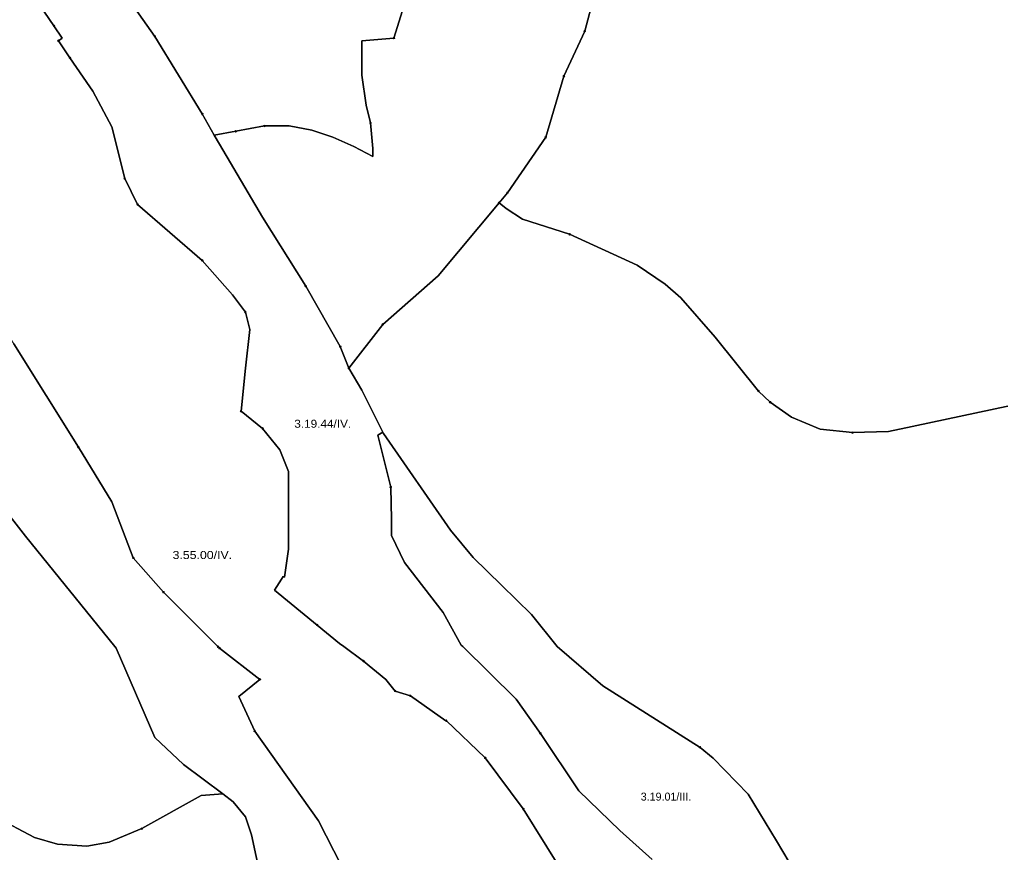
# Model space of a CAD drawing. Extents: x -650455 to -642254, y -1075222 to -1066610.
# Drawn here: x -646878 to -645652, y -1072257 to -1071216 of the extents above; entities that cross this region are included whole.
import ezdxf
from ezdxf.enums import TextEntityAlignment as Align

# ---------------------------------------------------------------- set-up
doc = ezdxf.new("R2010")
doc.units = 0
doc.header["$LTSCALE"] = 4
doc.header["$PDMODE"] = 32
doc.header["$PDSIZE"] = 2
for name, color, linetype, lineweight in [('1', 7, 'Continuous', 25), ('11', 7, 'Continuous', 13), ('12', 7, 'Continuous', 13), ('13', 7, 'Continuous', 13), ('14', 7, 'Continuous', 13)]:
    doc.layers.add(name, color=color, linetype=linetype, lineweight=lineweight)
doc.layers.add('2', color=7, linetype='Continuous')

msp = doc.modelspace()

# ---------------------------------------------------------------- linework, layer by layer
at = {"layer": '1'}
for points in [[(-646154.372, -1071165.527), (-646171.706, -1071230.527), (-646197.706, -1071286.861), (-646220.456, -1071363.237), (-646268.124, -1071432.571), (-646278.639, -1071445.19), (-646354.791, -1071536.572), (-646424.125, -1071597.24), (-646466.433, -1071651.884), (-646477.206, -1071624.953), (-646520.295, -1071549.547), (-646574.157, -1071463.368), (-646628.018, -1071371.803), (-646634.506, -1071360.45), (-646607.539, -1071355.754), (-646571.854, -1071349.129), (-646541.062, -1071349.053), (-646512.831, -1071354.248), (-646486.255, -1071363.056), (-646460.282, -1071374.876)], [(-646190.5, -1071484.501), (-646249.5, -1071465.5), (-646270, -1071452.5), (-646278.639, -1071445.19), (-646268.124, -1071432.571), (-646220.456, -1071363.237), (-646197.706, -1071286.861), (-646171.706, -1071230.527), (-646154.372, -1071165.527)], [(-646393.156, -1071184.317), (-646410.042, -1071239.194), (-646450.275, -1071242.536), (-646450.275, -1071285.625), (-646444.889, -1071323.328), (-646439.373, -1071345.392), (-646436.341, -1071377.436), (-646436.341, -1071387.223), (-646460.282, -1071374.876), (-646486.255, -1071363.056), (-646512.831, -1071354.248), (-646541.062, -1071349.053), (-646571.854, -1071349.129), (-646607.539, -1071355.754), (-646634.506, -1071360.45), (-646649.563, -1071334.1), (-646708.811, -1071237.149), (-646743.712, -1071187.194)], [(-646743.712, -1071187.194), (-646708.811, -1071237.149), (-646649.563, -1071334.1), (-646634.506, -1071360.45), (-646628.018, -1071371.803), (-646574.157, -1071463.368), (-646520.295, -1071549.547), (-646477.206, -1071624.953), (-646466.433, -1071651.884), (-646450.126, -1071679.574), (-646423.791, -1071731.896), (-646430, -1071735.501), (-646414, -1071800.501), (-646413, -1071841.001), (-646413, -1071861.001), (-646397, -1071895), (-646348.5, -1071957.501)], [(-646460.282, -1071374.876), (-646436.341, -1071387.223), (-646436.341, -1071377.436), (-646439.373, -1071345.392), (-646444.889, -1071323.328), (-646450.275, -1071285.625), (-646450.275, -1071242.536), (-646410.042, -1071239.194), (-646393.156, -1071184.317)], [(-646786.429, -1071305.826), (-646790.183, -1071300.284), (-646814.876, -1071263.836), (-646829.299, -1071242.546), (-646824.502, -1071239.296), (-646834.862, -1071224.003), (-646859.12, -1071188.198)], [(-646859.12, -1071188.198), (-646834.862, -1071224.003), (-646824.502, -1071239.296), (-646829.299, -1071242.546), (-646814.876, -1071263.836), (-646790.183, -1071300.284), (-646786.429, -1071305.826), (-646762.673, -1071350.259), (-646746.514, -1071414.893), (-646730.355, -1071447.21), (-646649.563, -1071517.23), (-646611.86, -1071560.319), (-646595.701, -1071581.864), (-646590.315, -1071603.408), (-646595.701, -1071651.884), (-646601.087, -1071705.746), (-646574.157, -1071727.29), (-646552.612, -1071754.221), (-646541.84, -1071781.152), (-646541.84, -1071829.627), (-646541.84, -1071878.103), (-646546.839, -1071913.101), (-646548.5, -1071912.501), (-646550.686, -1071915.879)], [(-646175.5, -1072320), (-646248.5, -1072203), (-646296, -1072139.001), (-646345, -1072092.5), (-646345.4, -1072092.965), (-646389.5, -1072061.5), (-646408.5, -1072055.501), (-646420, -1072041), (-646448, -1072018.001), (-646472.545, -1072000), (-646478, -1071996), (-646506, -1071973.001), (-646559.5, -1071929.501), (-646550.686, -1071915.879), (-646548.5, -1071912.501), (-646546.839, -1071913.101), (-646541.84, -1071878.103), (-646541.84, -1071829.627), (-646541.84, -1071781.152), (-646552.612, -1071754.221), (-646574.157, -1071727.29), (-646601.087, -1071705.746), (-646595.701, -1071651.884), (-646590.315, -1071603.408), (-646595.701, -1071581.864), (-646611.86, -1071560.319), (-646649.563, -1071517.23), (-646730.355, -1071447.21), (-646746.514, -1071414.893), (-646762.673, -1071350.259), (-646786.429, -1071305.826)], [(-645908.5, -1072283), (-645932, -1072243), (-645967.5, -1072184.501), (-646011, -1072139.501), (-646027.5, -1072126), (-646149, -1072049), (-646206, -1072000), (-646238, -1071960), (-646275.5, -1071923), (-646311, -1071888.501), (-646339.5, -1071854.5), (-646423.033, -1071733.402), (-646423.791, -1071731.896), (-646450.126, -1071679.574), (-646466.433, -1071651.884), (-646424.125, -1071597.24), (-646354.791, -1071536.572), (-646278.639, -1071445.19), (-646270, -1071452.5), (-646249.5, -1071465.5), (-646190.5, -1071484.501), (-646106, -1071523), (-646071, -1071547), (-646051.5, -1071564.001), (-646008.5, -1071613.001), (-645954.5, -1071680.5), (-645940, -1071694.501), (-645913.5, -1071713), (-645877.5, -1071728), (-645837, -1071732.5), (-645792, -1071731.001), (-645762.5, -1071725), (-645619.5, -1071694.501)], [(-645619.5, -1071694.501), (-645762.5, -1071725), (-645792, -1071731.001), (-645837, -1071732.5), (-645877.5, -1071728), (-645913.5, -1071713), (-645940, -1071694.501), (-645954.5, -1071680.5), (-646008.5, -1071613.001), (-646051.5, -1071564.001), (-646071, -1071547), (-646106, -1071523), (-646190.5, -1071484.501)], [(-646447, -1072330.501), (-646504.5, -1072218), (-646584, -1072105.5), (-646604, -1072062.501), (-646577.5, -1072041), (-646628.018, -1072001.985), (-646630.002, -1072000), (-646698.038, -1071931.964), (-646735.742, -1071888.875), (-646762.673, -1071818.855), (-646804.415, -1071750.855), (-646885.208, -1071621.587)], [(-646885.208, -1071621.587), (-646804.415, -1071750.855), (-646762.673, -1071818.855), (-646735.742, -1071888.875), (-646698.038, -1071931.964), (-646630.002, -1072000), (-646628.018, -1072001.985), (-646577.5, -1072041), (-646604, -1072062.501), (-646584, -1072105.5), (-646504.5, -1072218), (-646447, -1072330.501)], [(-646087.5, -1072266.001), (-646128, -1072230), (-646179, -1072180.501), (-646227, -1072108.5), (-646257.5, -1072065.5), (-646323.97, -1072000), (-646326, -1071998.001), (-646348.5, -1071957.501), (-646397, -1071895), (-646413, -1071861.001), (-646413, -1071841.001), (-646414, -1071800.501), (-646430, -1071735.501), (-646423.791, -1071731.896), (-646423.033, -1071733.402), (-646339.5, -1071854.5), (-646311, -1071888.501), (-646275.5, -1071923), (-646238, -1071960), (-646206, -1072000), (-646149, -1072049), (-646027.5, -1072126), (-646011, -1072139.501), (-645967.5, -1072184.501), (-645932, -1072243), (-645908.5, -1072283)], [(-646611, -1072194), (-646624, -1072184.001), (-646673, -1072147.501), (-646709, -1072113.5), (-646757.286, -1072001.985), (-646758.889, -1072000), (-646870.396, -1071861.944), (-646929.643, -1071786.538)], [(-646929.643, -1071786.538), (-646870.396, -1071861.944), (-646758.889, -1072000), (-646757.286, -1072001.985), (-646709, -1072113.5), (-646673, -1072147.501), (-646624, -1072184.001), (-646651, -1072186), (-646725, -1072227.5), (-646766, -1072244.501), (-646794, -1072249.501), (-646830.5, -1072247), (-646859, -1072238.5), (-646908.5, -1072213.001)], [(-646550.686, -1071915.879), (-646559.5, -1071929.501), (-646506, -1071973.001), (-646478, -1071996), (-646472.545, -1072000), (-646448, -1072018.001), (-646420, -1072041), (-646408.5, -1072055.501), (-646389.5, -1072061.5), (-646345.4, -1072092.965), (-646345, -1072092.5), (-646296, -1072139.001), (-646248.5, -1072203), (-646175.5, -1072320), (-646120.5, -1072383.001), (-646020, -1072481), (-646013.29, -1072487.101)], [(-646348.5, -1071957.501), (-646326, -1071998.001), (-646323.97, -1072000), (-646257.5, -1072065.5), (-646227, -1072108.5), (-646179, -1072180.501), (-646128, -1072230), (-646087.5, -1072266.001)], [(-646908.5, -1072213.001), (-646859, -1072238.5), (-646830.5, -1072247), (-646794, -1072249.501), (-646766, -1072244.501), (-646725, -1072227.5), (-646651, -1072186), (-646624, -1072184.001), (-646611, -1072194), (-646595.5, -1072213.001), (-646588, -1072235.5), (-646576.5, -1072289.501), (-646559.5, -1072345.501), (-646540.5, -1072384), (-646514.5, -1072420.001), (-646470, -1072469.5), (-646420, -1072512.501), (-646392, -1072535), (-646381, -1072550.5), (-646346.5, -1072604.501), (-646329.469, -1072644.503), (-646334, -1072702.501), (-646348, -1072738.501), (-646368, -1072765.5)], [(-646576.5, -1072289.501), (-646588, -1072235.5), (-646595.5, -1072213.001), (-646611, -1072194)]]:
    msp.add_lwpolyline(points, dxfattribs=at)
at = {"layer": '11'}
for p, q in [((-646197.706, -1071286.861), (-646220.456, -1071363.237)), ((-646220.456, -1071363.237), (-646268.124, -1071432.571)), ((-646630.002, -1072000), (-646698.038, -1071931.964))]:
    msp.add_line(p, q, dxfattribs=at)
for points in [[(-646197.487, -1070763.107), (-646171.706, -1070831.857), (-646145.706, -1070901.191), (-646141.372, -1070996.525), (-646145.706, -1071100.526), (-646154.372, -1071165.527), (-646171.706, -1071230.527), (-646197.706, -1071286.861)], [(-646268.124, -1071432.571), (-646278.639, -1071445.19), (-646270, -1071452.5), (-646249.5, -1071465.5), (-646190.5, -1071484.501)], [(-646698.038, -1071931.964), (-646735.742, -1071888.875), (-646762.673, -1071818.855), (-646804.415, -1071750.855), (-646885.208, -1071621.587), (-646992.931, -1071454.616)], [(-645954.5, -1071680.5), (-646008.5, -1071613.001), (-646051.5, -1071564.001), (-646071, -1071547), (-646106, -1071523), (-646190.5, -1071484.501), (-646249.5, -1071465.5), (-646270, -1071452.5), (-646278.639, -1071445.19), (-646354.791, -1071536.572), (-646424.125, -1071597.24), (-646466.433, -1071651.884)], [(-646190.5, -1071484.501), (-646106, -1071523), (-646071, -1071547), (-646051.5, -1071564.001), (-646008.5, -1071613.001), (-645954.5, -1071680.5), (-645940, -1071694.501)], [(-646466.433, -1071651.884), (-646450.126, -1071679.574), (-646423.791, -1071731.896), (-646423.033, -1071733.402), (-646339.5, -1071854.5), (-646311, -1071888.501), (-646275.5, -1071923), (-646238, -1071960), (-646206, -1072000), (-646149, -1072049), (-646027.5, -1072126)], [(-645837, -1071732.5), (-645792, -1071731.001), (-645762.5, -1071725), (-645619.5, -1071694.501), (-645493, -1071675.001), (-645451, -1071667.001), (-645411, -1071663), (-645381.5, -1071666.001), (-645306, -1071694.501)], [(-645493, -1071675.001), (-645619.5, -1071694.501), (-645762.5, -1071725), (-645792, -1071731.001), (-645837, -1071732.5), (-645877.5, -1071728), (-645913.5, -1071713), (-645940, -1071694.501), (-645954.5, -1071680.5)], [(-645940, -1071694.501), (-645913.5, -1071713), (-645877.5, -1071728), (-645837, -1071732.5)], [(-646908.5, -1072213.001), (-646859, -1072238.5), (-646830.5, -1072247), (-646794, -1072249.501), (-646766, -1072244.501), (-646725, -1072227.5), (-646651, -1072186), (-646624, -1072184.001), (-646673, -1072147.501), (-646709, -1072113.5), (-646757.286, -1072001.985), (-646758.889, -1072000), (-646870.396, -1071861.944), (-646929.643, -1071786.538)], [(-646929.643, -1071786.538), (-646870.396, -1071861.944), (-646758.889, -1072000), (-646757.286, -1072001.985), (-646709, -1072113.5), (-646673, -1072147.501), (-646624, -1072184.001), (-646611, -1072194), (-646595.5, -1072213.001), (-646588, -1072235.5), (-646576.5, -1072289.501), (-646559.5, -1072345.501), (-646540.5, -1072384)], [(-646584, -1072105.5), (-646604, -1072062.501), (-646577.5, -1072041), (-646628.018, -1072001.985), (-646630.002, -1072000)], [(-646725, -1072227.5), (-646766, -1072244.501), (-646794, -1072249.501), (-646830.5, -1072247), (-646859, -1072238.5), (-646908.5, -1072213.001), (-646971, -1072165.5), (-647106.5, -1072039.5)], [(-646346.5, -1072527.501), (-646337, -1072520.001), (-646337, -1072506), (-646381, -1072447.501), (-646419.5, -1072388.5), (-646447, -1072330.501), (-646504.5, -1072218), (-646584, -1072105.5)], [(-646027.5, -1072126), (-646011, -1072139.501), (-645967.5, -1072184.501), (-645932, -1072243), (-645908.5, -1072283), (-645884.5, -1072309.501), (-645854, -1072327), (-645788.5, -1072351.001), (-645718.5, -1072394.001), (-645697, -1072391.501), (-645594, -1072384.5), (-645567.5, -1072387.001), (-645560, -1072390.001), (-645550.5, -1072338.001), (-645549, -1072189.5), (-645544.5, -1072153.5), (-645532, -1072135.501), (-645510.5, -1072118.5), (-645474.5, -1072111.501), (-645421, -1072113), (-645398, -1072117), (-645373.5, -1072126), (-645338.5, -1072147.001)], [(-646559.5, -1072345.501), (-646576.5, -1072289.501), (-646588, -1072235.5), (-646595.5, -1072213.001), (-646611, -1072194), (-646624, -1072184.001), (-646651, -1072186), (-646725, -1072227.5)]]:
    msp.add_lwpolyline(points, dxfattribs=at)
for p in [(-646197.706, -1071286.861), (-646220.456, -1071363.237), (-646268.124, -1071432.571), (-646190.5, -1071484.501), (-646466.433, -1071651.884), (-645954.5, -1071680.5), (-645940, -1071694.501), (-645837, -1071732.5), (-646698.038, -1071931.964), (-646630.002, -1072000), (-646584, -1072105.5), (-646027.5, -1072126), (-646725, -1072227.5)]:
    msp.add_point(p, dxfattribs=at)
at = {"layer": '12'}
for p, q in [((-646197.706, -1071286.861), (-646171.706, -1071230.527)), ((-646278.639, -1071445.19), (-646268.124, -1071432.571))]:
    msp.add_line(p, q, dxfattribs=at)
for points in [[(-646171.706, -1071230.527), (-646154.372, -1071165.527), (-646145.706, -1071100.526), (-646141.372, -1070996.525), (-646145.706, -1070901.191), (-646171.706, -1070831.857), (-646197.487, -1070763.107), (-646197.659, -1070749.898)], [(-646396.096, -1071025.528), (-646393.156, -1071184.317), (-646410.042, -1071239.194)], [(-646410.042, -1071239.194), (-646450.275, -1071242.536), (-646450.275, -1071285.625), (-646444.889, -1071323.328), (-646439.373, -1071345.392)], [(-646268.124, -1071432.571), (-646220.456, -1071363.237), (-646197.706, -1071286.861)], [(-646439.373, -1071345.392), (-646436.341, -1071377.436), (-646436.341, -1071387.223), (-646460.282, -1071374.876), (-646486.255, -1071363.056), (-646512.831, -1071354.248), (-646541.062, -1071349.053), (-646571.854, -1071349.129), (-646607.539, -1071355.754), (-646634.506, -1071360.45), (-646628.018, -1071371.803), (-646574.157, -1071463.368), (-646520.295, -1071549.547), (-646477.206, -1071624.953)], [(-646424.125, -1071597.24), (-646354.791, -1071536.572), (-646278.639, -1071445.19)], [(-646477.206, -1071624.953), (-646466.433, -1071651.884), (-646424.125, -1071597.24)]]:
    msp.add_lwpolyline(points, dxfattribs=at)
for p in [(-646171.706, -1071230.527), (-646410.042, -1071239.194), (-646197.706, -1071286.861), (-646439.373, -1071345.392), (-646268.124, -1071432.571), (-646278.639, -1071445.19), (-646424.125, -1071597.24), (-646477.206, -1071624.953)]:
    msp.add_point(p, dxfattribs=at)
at = {"layer": '13'}
for p, q in [((-646708.811, -1071237.149), (-646649.563, -1071334.1)), ((-646607.539, -1071355.754), (-646571.854, -1071349.129))]:
    msp.add_line(p, q, dxfattribs=at)
for points in [[(-646677.628, -1070751.147), (-646699.295, -1070738.147), (-646729.628, -1070720.814), (-646751.296, -1070768.481), (-646768.629, -1070811.815), (-646799.029, -1070883.683), (-646815.187, -1070905.227), (-646831.346, -1070932.158), (-646869.049, -1070964.475), (-646804.415, -1071034.495), (-646782.712, -1071061.526), (-646782.712, -1071100.526), (-646769.712, -1071135.193), (-646743.712, -1071187.194), (-646708.811, -1071237.149)], [(-646410.042, -1071239.194), (-646393.156, -1071184.317), (-646396.096, -1071025.528), (-646392.694, -1071012.768)], [(-646571.854, -1071349.129), (-646541.062, -1071349.053), (-646512.831, -1071354.248), (-646486.255, -1071363.056), (-646460.282, -1071374.876), (-646436.341, -1071387.223), (-646436.341, -1071377.436), (-646439.373, -1071345.392), (-646444.889, -1071323.328), (-646450.275, -1071285.625), (-646450.275, -1071242.536), (-646410.042, -1071239.194)], [(-646649.563, -1071334.1), (-646634.506, -1071360.45), (-646607.539, -1071355.754)], [(-645908.5, -1072283), (-645932, -1072243), (-645967.5, -1072184.501), (-646011, -1072139.501), (-646027.5, -1072126), (-646149, -1072049), (-646206, -1072000), (-646238, -1071960), (-646275.5, -1071923), (-646311, -1071888.501), (-646339.5, -1071854.5), (-646423.033, -1071733.402), (-646423.791, -1071731.896), (-646430, -1071735.501), (-646414, -1071800.501), (-646413, -1071841.001), (-646413, -1071861.001), (-646397, -1071895), (-646348.5, -1071957.501), (-646326, -1071998.001), (-646323.97, -1072000), (-646257.5, -1072065.5), (-646227, -1072108.5), (-646179, -1072180.501), (-646128, -1072230), (-646087.5, -1072266.001)]]:
    msp.add_lwpolyline(points, dxfattribs=at)
for p in [(-646708.811, -1071237.149), (-646410.042, -1071239.194), (-646649.563, -1071334.1), (-646607.539, -1071355.754), (-646571.854, -1071349.129)]:
    msp.add_point(p, dxfattribs=at)
at = {"layer": '14'}
for p, q in [((-646730.355, -1071447.21), (-646649.563, -1071517.23)), ((-646885.208, -1071621.587), (-646804.415, -1071750.855)), ((-646628.018, -1072001.985), (-646577.5, -1072041)), ((-646408.5, -1072055.501), (-646389.5, -1072061.5)), ((-646296, -1072139.001), (-646345, -1072092.5))]:
    msp.add_line(p, q, dxfattribs=at)
for points in [[(-646829.299, -1071242.546), (-646824.502, -1071239.296), (-646834.862, -1071224.003), (-646859.12, -1071188.198), (-646868.599, -1071172.329), (-646871.388, -1071167.008)], [(-646868.599, -1071172.329), (-646859.12, -1071188.198), (-646834.862, -1071224.003)], [(-646649.563, -1071334.1), (-646708.811, -1071237.149), (-646743.712, -1071187.194)], [(-646834.862, -1071224.003), (-646824.502, -1071239.296), (-646829.299, -1071242.546), (-646814.876, -1071263.836)], [(-646746.514, -1071414.893), (-646762.673, -1071350.259), (-646786.429, -1071305.826), (-646790.183, -1071300.284), (-646814.876, -1071263.836), (-646829.299, -1071242.546)], [(-646814.876, -1071263.836), (-646790.183, -1071300.284), (-646786.429, -1071305.826), (-646762.673, -1071350.259), (-646746.514, -1071414.893), (-646730.355, -1071447.21)], [(-646520.295, -1071549.547), (-646574.157, -1071463.368), (-646628.018, -1071371.803), (-646634.506, -1071360.45), (-646649.563, -1071334.1)], [(-646595.701, -1071581.864), (-646611.86, -1071560.319), (-646649.563, -1071517.23), (-646730.355, -1071447.21), (-646746.514, -1071414.893)], [(-646649.563, -1071517.23), (-646611.86, -1071560.319), (-646595.701, -1071581.864), (-646590.315, -1071603.408), (-646595.701, -1071651.884), (-646601.087, -1071705.746), (-646574.157, -1071727.29)], [(-646414, -1071800.501), (-646430, -1071735.501), (-646423.791, -1071731.896), (-646450.126, -1071679.574), (-646466.433, -1071651.884), (-646477.206, -1071624.953), (-646520.295, -1071549.547)], [(-646601.087, -1071705.746), (-646595.701, -1071651.884), (-646590.315, -1071603.408), (-646595.701, -1071581.864)], [(-646448, -1072018.001), (-646472.545, -1072000), (-646478, -1071996), (-646506, -1071973.001), (-646559.5, -1071929.501), (-646550.686, -1071915.879), (-646548.5, -1071912.501), (-646546.839, -1071913.101), (-646541.84, -1071878.103), (-646541.84, -1071829.627), (-646541.84, -1071781.152), (-646552.612, -1071754.221), (-646574.157, -1071727.29), (-646601.087, -1071705.746)], [(-646574.157, -1071727.29), (-646552.612, -1071754.221), (-646541.84, -1071781.152), (-646541.84, -1071829.627), (-646541.84, -1071878.103), (-646546.839, -1071913.101)], [(-646804.415, -1071750.855), (-646762.673, -1071818.855), (-646735.742, -1071888.875)], [(-646227, -1072108.5), (-646257.5, -1072065.5), (-646323.97, -1072000), (-646326, -1071998.001), (-646348.5, -1071957.501), (-646397, -1071895), (-646413, -1071861.001), (-646413, -1071841.001), (-646414, -1071800.501)], [(-646735.742, -1071888.875), (-646698.038, -1071931.964), (-646630.002, -1072000), (-646628.018, -1072001.985)], [(-646546.839, -1071913.101), (-646548.5, -1071912.501), (-646550.686, -1071915.879), (-646559.5, -1071929.501), (-646506, -1071973.001)], [(-646506, -1071973.001), (-646478, -1071996), (-646472.545, -1072000), (-646448, -1072018.001), (-646420, -1072041), (-646408.5, -1072055.501)], [(-646345, -1072092.5), (-646345.4, -1072092.965), (-646389.5, -1072061.5), (-646408.5, -1072055.501), (-646420, -1072041), (-646448, -1072018.001)], [(-646577.5, -1072041), (-646604, -1072062.501), (-646584, -1072105.5), (-646504.5, -1072218), (-646447, -1072330.501), (-646419.5, -1072388.5), (-646381, -1072447.501)], [(-646389.5, -1072061.5), (-646345.4, -1072092.965), (-646345, -1072092.5), (-646296, -1072139.001), (-646248.5, -1072203)], [(-646087.5, -1072266.001), (-646128, -1072230), (-646179, -1072180.501), (-646227, -1072108.5)], [(-646175.5, -1072320), (-646248.5, -1072203), (-646296, -1072139.001)], [(-646248.5, -1072203), (-646175.5, -1072320), (-646120.5, -1072383.001), (-646020, -1072481), (-646013.29, -1072487.101), (-646005.6, -1072481.541), (-645979.711, -1072449.972), (-645952, -1072479.501), (-645903.5, -1072547), (-645924, -1072572.501)]]:
    msp.add_lwpolyline(points, dxfattribs=at)
for p in [(-646834.862, -1071224.003), (-646829.299, -1071242.546), (-646814.876, -1071263.836), (-646649.563, -1071334.1), (-646746.514, -1071414.893), (-646730.355, -1071447.21), (-646649.563, -1071517.23), (-646520.295, -1071549.547), (-646595.701, -1071581.864), (-646601.087, -1071705.746), (-646574.157, -1071727.29), (-646804.415, -1071750.855), (-646414, -1071800.501), (-646735.742, -1071888.875), (-646506, -1071973.001), (-646628.018, -1072001.985), (-646448, -1072018.001), (-646577.5, -1072041), (-646408.5, -1072055.501), (-646389.5, -1072061.5), (-646345, -1072092.5), (-646227, -1072108.5), (-646296, -1072139.001), (-646248.5, -1072203)]:
    msp.add_point(p, dxfattribs=at)

# ---------------------------------------------------------------- texts
at = {"layer": '2'}
for s, width, p in [('3.19.44/IV.', 1.1, (-646499.029, -1071726.402)), ('3.55.00/IV.', 1.15, (-646649.471, -1071890.494))]:
    msp.add_text(s, height=10, dxfattribs=dict(at, width=width)).set_placement(p, align=Align.CENTER)
msp.add_text('3.19.01/III.', height=10, dxfattribs=at).set_placement((-646070.114, -1072192.522), align=Align.CENTER)

doc.saveas('drawing.dxf')
